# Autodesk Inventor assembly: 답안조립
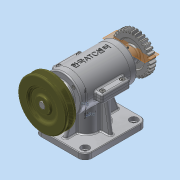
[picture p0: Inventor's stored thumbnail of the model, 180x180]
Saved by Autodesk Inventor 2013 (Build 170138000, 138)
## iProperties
Created: 2015-09
Part Number: 답안조립
Document SubType Name: Assembly
Designer: Administrator
Mass: 2251.16 g
Surface Area: 1633.52 cm^2
Volume: 528.514 cm^3
Density: 4.25942 g/cm^3
Author: Administrator
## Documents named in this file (17)
- C:\Users\Administrator\Desktop\350908V1011\답안조립.iam
- C:\Users\Administrator\Desktop\350908V1011\M3x0.5x8.ipt
- C:\Users\Administrator\Desktop\350908V1011\M4x0.5x14.ipt
- C:\Users\Administrator\Desktop\350908V1011\V-벨트풀리.ipt
- C:\Users\Administrator\Desktop\350908V1011\뒤커버.ipt
- C:\Users\Administrator\Desktop\350908V1011\멈춤나사.ipt
- C:\Users\Administrator\Desktop\350908V1011\베어링 6201.ipt
- C:\Users\Administrator\Desktop\350908V1011\베어링 6202.ipt
- C:\Users\Administrator\Desktop\350908V1011\본체 커버.ipt
- C:\Users\Administrator\Desktop\350908V1011\본체.ipt
- C:\Users\Administrator\Desktop\350908V1011\스퍼기어.ipt
- C:\Users\Administrator\Desktop\350908V1011\스프링 - [가변].ipt
- C:\Users\Administrator\Desktop\350908V1011\슬라이드.ipt
- C:\Users\Administrator\Desktop\350908V1011\앞커버.ipt
- C:\Users\Administrator\Desktop\350908V1011\오일실.ipt
- C:\Users\Administrator\Desktop\350908V1011\키4x4.ipt
- C:\Users\Administrator\Desktop\350908V1011\편심축.ipt
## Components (13 placed, 3 different names)
1. M4x0.5x14:1
2. V-벨트풀리:1 — 플러쉬:3
3. M4x0.5x14:2
4. M4x0.5x14:3
5. M4x0.5x14:4
6. M3x0.5x8:1
7. M3x0.5x8:3
8. M3x0.5x8:4
9. M3x0.5x8:5
10. M3x0.5x8:2
11. M3x0.5x8:6
12. M3x0.5x8:7
13. M3x0.5x8:8
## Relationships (1: Flush 1)
- 플러쉬:3 [Flush]: V-벨트풀리:1
